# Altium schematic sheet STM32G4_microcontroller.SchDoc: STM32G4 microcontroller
size A4; Date: Not used; ApprovedBy: Not used; CheckedBy: Not used; Author: Not used; CompanyName: STMicroelectronics; DrawnBy: Not used; Engineer: Not used; Organization: Not used; Address1: Not used; Address2: Not used; Address3: Not used; Address4: Not used; DocumentNumber: Not used; Revision: Not used; SheetNumber: 3; SheetTotal: 7
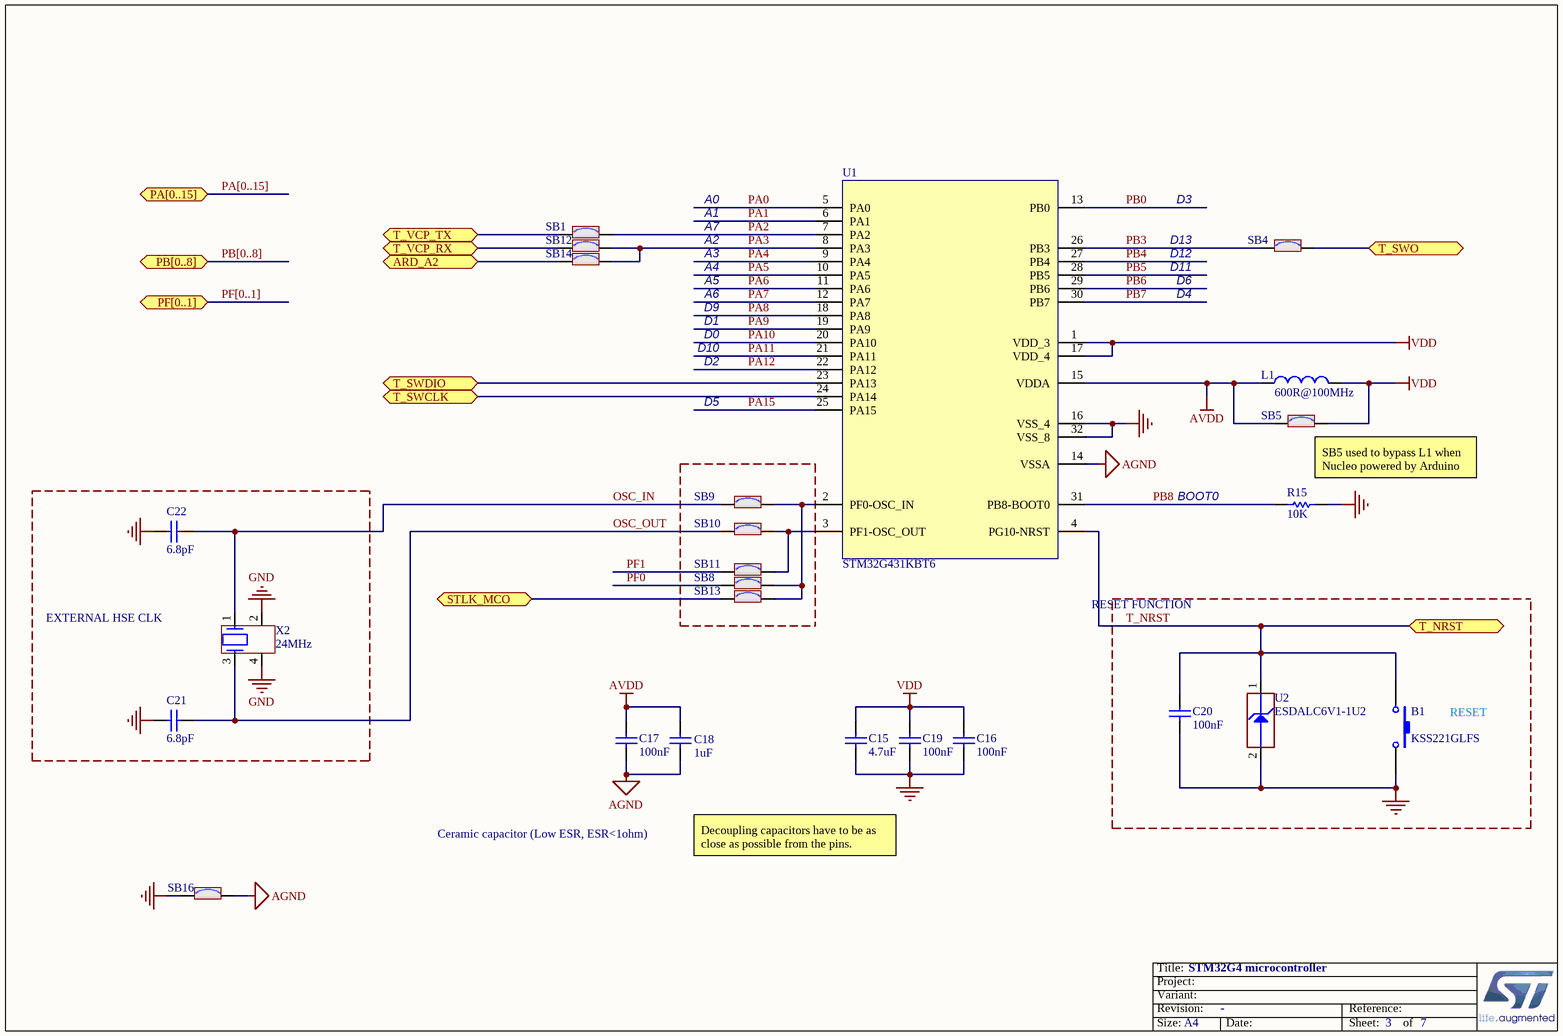
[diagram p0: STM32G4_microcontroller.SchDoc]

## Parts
B1  value KSS221GLFS  [SWI_C&K_ITT_KSS221G]
C15  value 4.7uF  [C0603]
C16  value 100nF  [C0402]
C17  value 100nF  [C0402]
C18  value 1uF  [C0603]
C19  value 100nF  [C0402]
C20  value 100nF  [C0402]
C21  value 6.8pF  [C0402]
C22  value 6.8pF  [C0402]
L1  value 600R@100MHz  [L0603]
R15  value 10K  [R0603]
SB1  (no value)  [SOLDER-BRIDGE_R0603-0R]
SB4  (no value)  [SOLDER-BRIDGE_R0603-0R]
SB5  (no value)  [SOLDER-BRIDGE_R0603-0R]
SB8  (no value)  [SOLDER-BRIDGE_R0603-0R]
SB9  (no value)  [SOLDER-BRIDGE_R0603-0R]
SB10  (no value)  [SOLDER-BRIDGE_R0603-0R]
SB11  (no value)  [SOLDER-BRIDGE_R0603-0R]
SB12  (no value)  [SOLDER-BRIDGE_R0603-0R]
SB13  (no value)  [SOLDER-BRIDGE_R0603-0R]
SB14  (no value)  [SOLDER-BRIDGE_R0603-0R]
SB16  (no value)  [SOLDER-BRIDGE_R0603-0R]
U1  value STM32G431KBT6  [ICC_LQFP32_7X7_P080__UFQFPN32-EPAD_5X5_P050__DI]
U2  value ESDALC6V1-1U2  [ESD_ST0201]
X2  value 24MHz  [CRY_NX2016SA_4P]

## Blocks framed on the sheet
EXTERNAL HSE CLK: C21 C22 X2

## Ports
ARD_A2, PA[0..15] (bidir), PB[0..8] (bidir), PF[0..1] (bidir), STLK_MCO, T_NRST, T_SWCLK, T_SWDIO, T_SWO, T_VCP_RX, T_VCP_TX

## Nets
AGND: C17.1 C18.1 SB16.2 U1.14(VSSA)
AVDD: C17.2 C18.2 L1.1 SB5.1 U1.15(VDDA)
GND: B1.2 C15.1 C16.1 C19.1 C20.1 C21.1 C22.1 R15.1 SB16.1 U1.16(VSS_4) U1.32(VSS_8) U2.2(GND) X2.2 X2.4
VDD: C15.2 C16.2 C19.2 L1.2 SB5.2 U1.1(VDD_3) U1.17(VDD_4)
ARD_A2: SB14.1 ; port ARD_A2
OSC_IN: C22.2 SB9.1 X2.1
OSC_OUT: C21.2 SB10.1 X2.3
PA0: U1.5(PA0)
PA1: U1.6(PA1)
PA2: SB1.2 U1.7(PA2)
PA3: SB12.2 SB14.2 U1.8(PA3)
PA4: U1.9(PA4)
PA5: U1.10(PA5)
PA6: U1.11(PA6)
PA7: U1.12(PA7)
PA8: U1.18(PA8)
PA9: U1.19(PA9)
PA10: U1.20(PA10)
PA11: U1.21(PA11)
PA12: U1.22(PA12)
PA15: U1.25(PA15)
PB0: U1.13(PB0)
PB3: SB4.1 U1.26(PB3)
PB4: U1.27(PB4)
PB5: U1.28(PB5)
PB6: U1.29(PB6)
PB7: U1.30(PB7)
PB8: R15.2 U1.31(PB8-BOOT0)
PF0: SB8.1
PF1: SB11.1
STLK_MCO: SB13.1 ; port STLK_MCO
T_NRST: B1.1 C20.2 U1.4(PG10-NRST) U2.1(IO1) ; port T_NRST
T_SWCLK: U1.24(PA14) ; port T_SWCLK
T_SWDIO: U1.23(PA13) ; port T_SWDIO
T_SWO: SB4.2 ; port T_SWO
T_VCP_RX: SB12.1 ; port T_VCP_RX
T_VCP_TX: SB1.1 ; port T_VCP_TX
NetSB8_2: SB8.2 SB9.2 SB13.2 U1.2(PF0-OSC_IN)
NetSB10_2: SB10.2 SB11.2 U1.3(PF1-OSC_OUT)

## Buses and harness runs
bus PA[0..15] = port PA[0..15]
bus PB[0..8] = port PB[0..8]
bus PF[0..1] = port PF[0..1]

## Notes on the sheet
- A0
- A1
- A2
- A7
- D13
- D3
- D9
- A3
- A4
- A5
- A6
- D12
- D11
- D4
- D6
- D1
- D0
- D10
- D2
- D5
- (near R15) BOOT0
- (near SB5) SB5 used to bypass L1 when Nucleo powered by Arduino AVDD.
- RESET FUNCTION
- RESET
- Ceramic capacitor (Low ESR, ESR<1ohm)
- Decoupling capacitors have to be as close as possible from the pins.

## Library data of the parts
B1 = MCD-01335: Subminiature Side Actuated Tact Switch for SMT - KSS series - 2.0 Newtons - Gull wing, SPST; Part_Type: Misc; Manufacturer: C&K; Provided_By: SUBCO; Initial_Board_Reference: MB1430
C15 = MCD-00009: Capacitor, MLCC, 4.7uF, 16V, X5R, 10%, 0603, T=0.8mm; Manufacturer_Part_Number: CC0603KRX5R7BB475; Manufacturer: YAGEO; Provided_By: SUBCO; Initial_Board_Reference: MB1274
C16 C17 C19 C20 = MCD-00102: Capacitor, MLCC, 100nF, 16V, X7R, 10%, 0402, T=0,5mm; Manufacturer_Part_Number: CC0402KRX7R7BB104; Manufacturer: YAGEO; Provided_By: SUBCO; Initial_Board_Reference: MB1262
C18 = MCD-00010: Capacitor, MLCC, 1uF, 16V, X5R, 10%, 0603, T=0,8mm; Manufacturer_Part_Number: CC0603KRX5R7BB105; Manufacturer: YAGEO; Provided_By: SUBCO; Initial_Board_Reference: MB1274
C21 C22 = MCD-00674: Capacitor, MLCC, 6.8pF, 50V, NPO, +-0.25pF, 0402, T=0.5mm; Manufacturer_Part_Number: CC0402CRNPO9BN6R8; Manufacturer: YAGEO; Provided_By: SUBCO; Initial_Board_Reference: MB1319
L1 = MCD-00047: SMD Chip ferrite bead, 600R@100MHz +/-25%, 350mA, 500mohm DC, 0603, T=0.8mm; Part_Type: Inductor; Manufacturer_Part_Number: FCM1608KF-601T03; Manufacturer: TAI-TECH; Provided_By: SUBCO; Initial_Board_Reference: MB1274
R15 = MCD-00220: Resistor,10K,0603,1%,1/10W; Manufacturer_Part_Number: RC0603FR-0710KL; Manufacturer: YAGEO; Provided_By: SUBCO; Initial_Board_Reference: MB1319
SB1 SB4 SB5 SB8-SB14 SB16 = MCD-00071: Solder Bridge ON; Part_Type: Mechanical; Manufacturer_Part_Number: RC0603JR-070RL; Manufacturer: YAGEO; Provided_By: SUBCO; Initial_Board_Reference: MB1274
U1 = MCD-01396: STM32G431, LQFP32 package, with double footprint (LQFP32_5V & UFQFPN32_A0B8); Part_Type: IC; Manufacturer: STMICROELECTRONICS; Provided_By: SUBCO with ST control; Initial_Board_Reference: MB1430
U2 = MCD-00170: ESD protection 6V1; Part_Type: Diode; Manufacturer: STMICROELECTRONICS; BMS_Part_Number: 9151132; Provided_By: SUBCO with ST control; Initial_Board_Reference: MB1274
X2 = MCD-01036: 24MHz crystal oscillator - Cl:6pf -; Part_Type: Crystal_Osc; Manufacturer_Part_Number: NX2016SA 24MHz EXS00A-CS10820; Manufacturer: NDK; Provided_By: ST; Initial_Board_Reference: MB1332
